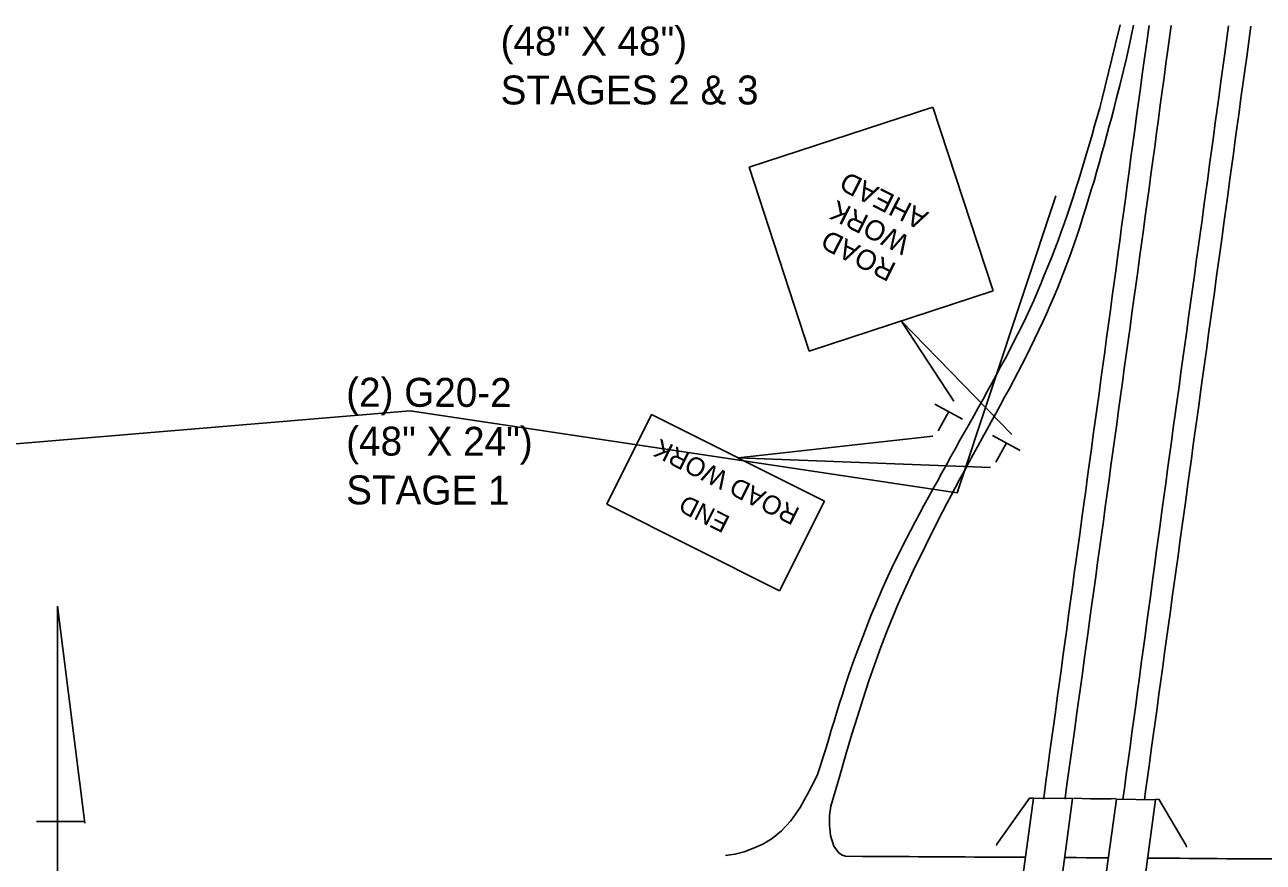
# Model space of a CAD drawing. Extents: x 1017892 to 1236694, y 658811 to 792468.
# Drawn here: x 1023342 to 1024005, y 660145 to 660594 of the extents above; entities that cross this region are included whole.
import ezdxf

# ---------------------------------------------------------------- set-up
doc = ezdxf.new("R2010")
doc.units = 0
for name, color, linetype in [('Level 3', 7, 'Continuous'), ('Level 42', 7, 'Continuous'), ('Level 8', 7, 'Continuous'), ('R_Border', 7, 'Continuous'), ('R_Draft', 7, 'Continuous'), ('R_Proposed Road Annot', 7, 'Continuous'), ('S_BRIDGE', 7, 'Continuous'), ('S_EDGE_PAVEMENT', 7, 'Continuous'), ('S_MISC_STRUCTURES', 7, 'Continuous'), ('S_SIDEWALK', 7, 'Continuous')]:
    doc.layers.add(name, color=color, linetype=linetype)

msp = doc.modelspace()

# ---------------------------------------------------------------- linework, layer by layer
at = {"layer": 'Level 3'}
for p, q in [((1023829.45, 660390.63), (1023844.26, 660382.56)), ((1023836.7, 660386.4), (1023831.19, 660376.28)), ((1023860.34, 660373.87), (1023875.16, 660365.79)), ((1023867.6, 660369.64), (1023862.09, 660359.52))]:
    msp.add_line(p, q, dxfattribs=at)
at = {"layer": 'Level 8'}
for p, q in [((1023729.88, 660517.64), (1023828.38, 660549.81)), ((1023828.38, 660549.81), (1023860.63, 660451.34)), ((1023729.88, 660517.64), (1023762.1, 660419.11)), ((1023762.1, 660419.11), (1023860.63, 660451.34)), ((1023677.64, 660385.07), (1023653.58, 660337.03)), ((1023677.64, 660385.07), (1023770.29, 660338.67)), ((1023770.29, 660338.67), (1023746.23, 660290.63)), ((1023653.58, 660337.03), (1023746.23, 660290.63))]:
    msp.add_line(p, q, dxfattribs=at)
at = {"layer": 'R_Border'}
for points in [[(1023894.3, 660502.31), (1023841.44, 660343.16), (1023548.14, 660387)], [(1023548.14, 660387), (1023255.62, 660362.67), (1022921.74, 660121.31)]]:
    msp.add_lwpolyline(points, dxfattribs=at)
at = {"layer": 'R_Draft'}
for p, q in [((1023359.24, 660282.45), (1023373.81, 660166.07)), ((1023359.24, 660119.74), (1023359.24, 660282.45)), ((1023347.96, 660166.94), (1023373.82, 660166.94))]:
    msp.add_line(p, q, dxfattribs=at)
at = {"layer": 'R_Proposed Road Annot'}
for p, q in [((1023839.65, 660392.26), (1023811.37, 660435.23)), ((1023811.37, 660435.23), (1023870.62, 660374.48)), ((1023828.39, 660373.5), (1023723.96, 660361.87)), ((1023723.96, 660361.87), (1023859.18, 660356.64))]:
    msp.add_line(p, q, dxfattribs=at)
at = {"layer": 'S_BRIDGE'}
for points in [[(1023870.29, 660091.63), (1023882.29, 660179.51), (1023903.23, 660179.39), (1023891.6, 660091.96), (1023870.29, 660091.63)], [(1023914.64, 660091.36), (1023926.73, 660179.01), (1023947.73, 660178.64), (1023935.89, 660091.13), (1023914.64, 660091.36)]]:
    msp.add_lwpolyline(points, dxfattribs=at)
at = {"layer": 'S_EDGE_PAVEMENT'}
for points in [[(1023928.79, 660594), (1023926.09, 660583.08), (1023924.27, 660575.77), (1023922.46, 660568.46), (1023920.65, 660561.15), (1023918.84, 660553.83), (1023917.76, 660549.49), (1023916.4, 660544.68), (1023915.05, 660539.87), (1023913.69, 660535.05), (1023912.3, 660530.25), (1023910.91, 660525.45), (1023909.51, 660520.65), (1023908.03, 660515.88), (1023906.55, 660511.1), (1023905.07, 660506.33), (1023903.59, 660501.55), (1023901.99, 660496.86), (1023900.5, 660492.51), (1023898.88, 660487.78), (1023897.17, 660483.08), (1023895.47, 660478.38), (1023893.76, 660473.68), (1023891.87, 660469.06), (1023889.97, 660464.43), (1023888.08, 660459.81), (1023886.19, 660455.18), (1023884.3, 660450.56), (1023882.55, 660446.3), (1023880.46, 660441.84), (1023878.33, 660437.31), (1023876.21, 660432.79), (1023873.92, 660428.34), (1023871.64, 660423.9), (1023869.35, 660419.45), (1023867.07, 660415.01), (1023864.68, 660410.62), (1023862.3, 660406.23), (1023859.91, 660401.84), (1023857.53, 660397.45), (1023855.14, 660393.06), (1023852.69, 660388.71), (1023850.23, 660384.36), (1023847.78, 660380.01), (1023845.32, 660375.67), (1023842.86, 660371.32), (1023840.41, 660366.97), (1023838, 660362.59), (1023835.59, 660358.21), (1023833.19, 660353.83), (1023830.78, 660349.46), (1023828.37, 660345.09), (1023825.96, 660340.72), (1023823.54, 660336.34), (1023821.2, 660331.93), (1023818.86, 660327.52), (1023816.52, 660323.11), (1023814.23, 660318.68), (1023811.93, 660314.24), (1023809.71, 660309.77), (1023807.49, 660305.29)], [(1023817.99, 660301.62), (1023820.19, 660306.1), (1023822.39, 660310.58), (1023824.59, 660315.06), (1023826.8, 660319.54), (1023829, 660324.02), (1023831.29, 660328.46), (1023833.58, 660332.89), (1023835.87, 660337.33), (1023838.16, 660341.76), (1023840.52, 660346.16), (1023842.89, 660350.56), (1023845.26, 660354.95), (1023847.62, 660359.35), (1023850.03, 660363.72), (1023852.44, 660368.09), (1023854.86, 660372.46), (1023857.25, 660376.85), (1023859.64, 660381.23), (1023862.03, 660385.61), (1023864.44, 660389.99), (1023866.84, 660394.37), (1023869.25, 660398.74), (1023871.58, 660403.16), (1023873.9, 660407.58), (1023876.23, 660412.01), (1023878.46, 660416.48), (1023880.69, 660420.94), (1023882.92, 660425.41), (1023885.01, 660429.96), (1023887.09, 660434.51), (1023889.18, 660439.05), (1023891.3, 660443.66), (1023893.35, 660448.6), (1023895.27, 660453.21), (1023897.14, 660457.85), (1023899, 660462.48), (1023900.73, 660467.17), (1023902.46, 660471.86), (1023904.08, 660476.59), (1023905.71, 660481.32), (1023907.24, 660486.08), (1023908.78, 660490.85), (1023910.39, 660495.87), (1023911.84, 660500.68), (1023913.29, 660505.47), (1023914.73, 660510.25), (1023916.09, 660515.07), (1023917.45, 660519.88), (1023918.81, 660524.69), (1023920.13, 660529.51), (1023921.44, 660534.33), (1023922.76, 660539.15), (1023924.08, 660543.97), (1023925.32, 660548.82), (1023926.68, 660554.11), (1023928.55, 660561.43), (1023930.42, 660568.74), (1023932.06, 660576.09), (1023933.69, 660583.43), (1023935.98, 660593.73)], [(1023944.21, 660593.67), (1023942.64, 660582.22), (1023941.62, 660574.79), (1023940.6, 660567.36), (1023939.58, 660559.93), (1023938.56, 660552.5), (1023937.54, 660545.07), (1023936.54, 660537.64), (1023935.54, 660530.2), (1023934.54, 660522.77), (1023933.54, 660515.34), (1023932.54, 660507.91), (1023931.54, 660500.47), (1023930.54, 660493.04), (1023929.54, 660485.61), (1023928.54, 660478.18), (1023927.54, 660470.75), (1023926.54, 660463.32), (1023925.54, 660455.88), (1023924.54, 660448.45), (1023923.54, 660441.02), (1023922.54, 660433.59), (1023921.51, 660426.16), (1023920.49, 660418.73), (1023919.47, 660411.3), (1023918.45, 660403.87), (1023917.42, 660396.44), (1023916.4, 660389.01), (1023915.38, 660381.58), (1023914.36, 660374.15), (1023913.33, 660366.73), (1023912.31, 660359.3), (1023911.29, 660351.87), (1023910.27, 660344.44), (1023909.26, 660337.01), (1023908.24, 660329.58), (1023907.22, 660322.15), (1023906.21, 660314.72), (1023905.19, 660307.29), (1023904.17, 660299.86), (1023903.16, 660292.43), (1023902.14, 660285), (1023901.12, 660277.57), (1023900.11, 660270.14), (1023899.09, 660262.71), (1023898.07, 660255.28), (1023897.06, 660247.85), (1023896.04, 660240.42), (1023895.02, 660232.99), (1023894.01, 660225.57), (1023892.99, 660218.13), (1023891.97, 660210.7), (1023890.96, 660203.27), (1023889.95, 660195.84), (1023888.99, 660188.4), (1023887.94, 660180.98), (1023887.61, 660178.99)], [(1023899.14, 660178.92), (1023899.22, 660179.43), (1023900.23, 660186.86), (1023901.24, 660194.29), (1023902.32, 660201.71), (1023903.35, 660209.14), (1023904.37, 660216.57), (1023905.4, 660223.99), (1023906.42, 660231.42), (1023907.45, 660238.85), (1023908.47, 660246.28), (1023909.5, 660253.71), (1023910.52, 660261.14), (1023911.55, 660268.56), (1023912.57, 660275.99), (1023913.59, 660283.42), (1023914.62, 660290.85), (1023915.64, 660298.28), (1023916.66, 660305.71), (1023917.68, 660313.14), (1023918.71, 660320.57), (1023919.73, 660328), (1023920.75, 660335.43), (1023921.77, 660342.86), (1023922.79, 660350.29), (1023923.82, 660357.72), (1023924.84, 660365.15), (1023925.86, 660372.58), (1023926.88, 660380.01), (1023927.91, 660387.44), (1023928.93, 660394.87), (1023929.95, 660402.3), (1023930.97, 660409.73), (1023932, 660417.16), (1023933.02, 660424.58), (1023934.04, 660432.01), (1023935.06, 660439.44), (1023936.08, 660446.87), (1023937.11, 660454.3), (1023938.13, 660461.73), (1023939.15, 660469.16), (1023940.17, 660476.59), (1023941.18, 660484.02), (1023942.19, 660491.45), (1023943.2, 660498.88), (1023944.21, 660506.32), (1023945.22, 660513.75), (1023946.23, 660521.18), (1023947.24, 660528.61), (1023948.25, 660536.04), (1023949.26, 660543.47), (1023950.27, 660550.9), (1023951.28, 660558.33), (1023952.3, 660565.76), (1023953.31, 660573.19), (1023954.32, 660580.63), (1023956.08, 660593.58)], [(1023986.84, 660593.37), (1023984.81, 660578.51), (1023983.79, 660571.07), (1023982.78, 660563.64), (1023981.76, 660556.21), (1023980.75, 660548.78), (1023979.73, 660541.35), (1023978.72, 660533.92), (1023977.7, 660526.49), (1023976.69, 660519.06), (1023975.67, 660511.63), (1023974.66, 660504.2), (1023973.65, 660496.77), (1023972.63, 660489.34), (1023971.62, 660481.91), (1023970.6, 660474.48), (1023969.57, 660467.05), (1023968.55, 660459.63), (1023967.52, 660452.2), (1023966.49, 660444.77), (1023965.46, 660437.34), (1023964.44, 660429.91), (1023963.41, 660422.48), (1023962.38, 660415.06), (1023961.35, 660407.63), (1023960.32, 660400.2), (1023959.3, 660392.77), (1023958.27, 660385.34), (1023957.24, 660377.91), (1023956.21, 660370.49), (1023955.19, 660363.06), (1023954.16, 660355.62), (1023953.15, 660348.19), (1023952.15, 660340.76), (1023951.14, 660333.33), (1023950.14, 660325.9), (1023949.13, 660318.46), (1023948.13, 660311.03), (1023947.13, 660303.6), (1023946.12, 660296.17), (1023945.12, 660288.74), (1023944.11, 660281.31), (1023943.11, 660273.87), (1023942.1, 660266.44), (1023941.1, 660259.01), (1023940.09, 660251.58), (1023939.09, 660244.15), (1023938.09, 660236.72), (1023937.08, 660229.28), (1023936.08, 660221.85), (1023935.07, 660214.42), (1023934.07, 660206.99), (1023933.06, 660199.55), (1023932.02, 660192.13), (1023931, 660184.7), (1023930.26, 660178.69)], [(1023941.8, 660178.63), (1023942.39, 660183.15), (1023943.37, 660190.59), (1023944.39, 660198.02), (1023945.41, 660205.45), (1023946.44, 660212.88), (1023947.46, 660220.3), (1023948.49, 660227.73), (1023949.51, 660235.16), (1023950.54, 660242.58), (1023951.56, 660250.01), (1023952.59, 660257.44), (1023953.61, 660264.87), (1023954.64, 660272.3), (1023955.66, 660279.73), (1023956.68, 660287.16), (1023957.71, 660294.59), (1023958.73, 660302.02), (1023959.76, 660309.45), (1023960.78, 660316.87), (1023961.81, 660324.3), (1023962.83, 660331.73), (1023963.86, 660339.16), (1023964.88, 660346.59), (1023965.91, 660354.02), (1023966.93, 660361.44), (1023967.96, 660368.87), (1023968.99, 660376.3), (1023970.01, 660383.73), (1023971.04, 660391.15), (1023972.07, 660398.58), (1023973.09, 660406.01), (1023974.12, 660413.44), (1023975.15, 660420.87), (1023976.17, 660428.3), (1023977.2, 660435.73), (1023978.23, 660443.15), (1023979.25, 660450.58), (1023980.28, 660458.01), (1023981.31, 660465.44), (1023982.33, 660472.87), (1023983.35, 660480.3), (1023984.37, 660487.73), (1023985.38, 660495.16), (1023986.4, 660502.59), (1023987.41, 660510.02), (1023988.43, 660517.45), (1023989.44, 660524.88), (1023990.46, 660532.32), (1023991.47, 660539.75), (1023992.49, 660547.18), (1023993.5, 660554.61), (1023994.52, 660562.04), (1023995.53, 660569.47), (1023996.55, 660576.9), (1023998.79, 660593.3)], [(1023757.29, 660174.42), (1023759.59, 660178.68), (1023762, 660183.16), (1023762.31, 660183.72), (1023764.44, 660187.63), (1023766.55, 660192.2), (1023768.13, 660196.94), (1023769.61, 660201.66), (1023771.1, 660206.43), (1023772.52, 660211.22), (1023773.93, 660216.01), (1023775.39, 660220.79), (1023776.84, 660225.57), (1023778.3, 660230.35), (1023779.85, 660235.1), (1023781.41, 660239.85), (1023782.96, 660244.61), (1023784.61, 660249.33), (1023786.36, 660254.32), (1023788.13, 660259), (1023789.91, 660263.68), (1023791.69, 660268.35), (1023793.47, 660273.03), (1023795.36, 660277.66), (1023797.24, 660282.29), (1023799.2, 660286.89), (1023801.16, 660291.49), (1023803.24, 660296.02), (1023805.33, 660300.56), (1023807.49, 660305.29)], [(1023817.99, 660301.62), (1023813.83, 660292.76), (1023809.8, 660283.62), (1023804.03, 660269.78), (1023800.51, 660260.41), (1023797.11, 660250.98), (1023794.09, 660242.31), (1023790.94, 660232.81), (1023787.9, 660223.29), (1023784.88, 660213.76), (1023782.05, 660204.17), (1023777.89, 660189.65), (1023773.76, 660175.23), (1023772.92, 660170.25), (1023773.04, 660164.96), (1023773.56, 660159.54), (1023775.37, 660153.72), (1023776.63, 660151.75), (1023777.92, 660150.22), (1023779.82, 660148.95), (1023781.59, 660148.33)], [(1023717.25, 660148.79), (1023722.25, 660149.46), (1023727.25, 660150.74), (1023732.26, 660152.61), (1023737.26, 660154.85), (1023742.26, 660157.9), (1023747.27, 660162.01), (1023752.28, 660167.25), (1023757.29, 660174.42)], [(1023781.59, 660148.33), (1023790.66, 660148.28), (1023795.66, 660148.25), (1023800.66, 660148.23), (1023805.66, 660148.2), (1023810.65, 660148.17), (1023815.66, 660148.14), (1023820.66, 660148.11), (1023825.65, 660148.09), (1023830.66, 660148.06), (1023835.66, 660148.03), (1023840.66, 660148), (1023845.65, 660147.97), (1023850.66, 660147.94), (1023855.66, 660147.92), (1023860.66, 660147.89), (1023865.66, 660147.86), (1023870.34, 660147.83), (1023875.28, 660147.81), (1023877.96, 660147.79)], [(1023899.01, 660147.67), (1023905.29, 660147.63), (1023910.56, 660147.59), (1023915.77, 660147.55), (1023922.39, 660147.54)], [(1023943.5, 660147.39), (1023955.78, 660147.3), (1023960.78, 660147.26), (1023965.78, 660147.22), (1023970.78, 660147.19), (1023975.78, 660147.14), (1023980.78, 660147.09), (1023985.78, 660147.04), (1023990.78, 660147.03), (1023995.78, 660147), (1024000.78, 660146.97), (1024005.78, 660146.94), (1024010.78, 660146.89), (1024015.78, 660146.88), (1024020.78, 660146.87), (1024044.68, 660146.8)]]:
    msp.add_lwpolyline(points, dxfattribs=at)
at = {"layer": 'S_MISC_STRUCTURES'}
msp.add_lwpolyline([(1023926.28, 660179.29), (1023923.92, 660179.18), (1023912.93, 660179.08), (1023903.89, 660179.43)], dxfattribs=at)
at = {"layer": 'S_SIDEWALK'}
for points in [[(1023882.41, 660179.5), (1023880.1, 660179.45), (1023862.62, 660154.75), (1023862.46, 660154.05)], [(1023964.22, 660153.21), (1023964.19, 660154.06), (1023949.42, 660178.92), (1023947.62, 660178.83)]]:
    msp.add_lwpolyline(points, dxfattribs=at)

# ---------------------------------------------------------------- texts
at = {"layer": 'Level 3'}
msp.add_text('ROAD WORK', height=10.075, rotation=153.39681, dxfattribs=at).set_placement((1023757.69, 660334.46))
at = {"layer": 'Level 42'}
msp.add_text('END', height=9.762, rotation=153.39681, dxfattribs=at).set_placement((1023720.3, 660330.06))
at = {"layer": 'Level 8'}
for s, p in [('(48" X 48")', (1023596.69, 660577.52)), ('STAGES 2 & 3', (1023596.69, 660551.29))]:
    msp.add_text(s, height=15.5, dxfattribs=at).set_placement(p)
for s, height, rotation, p in [('AHEAD', 10.799, 153.10798, (1023826.61, 660493.21)), ('WORK', 10.799, 153.10745, (1023816.94, 660479.95)), ('ROAD', 10.799, 153.10786, (1023809.42, 660465.6)), ('(2) G20-2', 15.5, 359.87782, (1023513.91, 660389.33)), ('(48" X 24")', 15.5, 359.87782, (1023513.91, 660363.15)), ('STAGE 1', 15.5, 359.87782, (1023513.91, 660336.97))]:
    msp.add_text(s, height=height, rotation=rotation, dxfattribs=at).set_placement(p)

doc.saveas('drawing.dxf')
